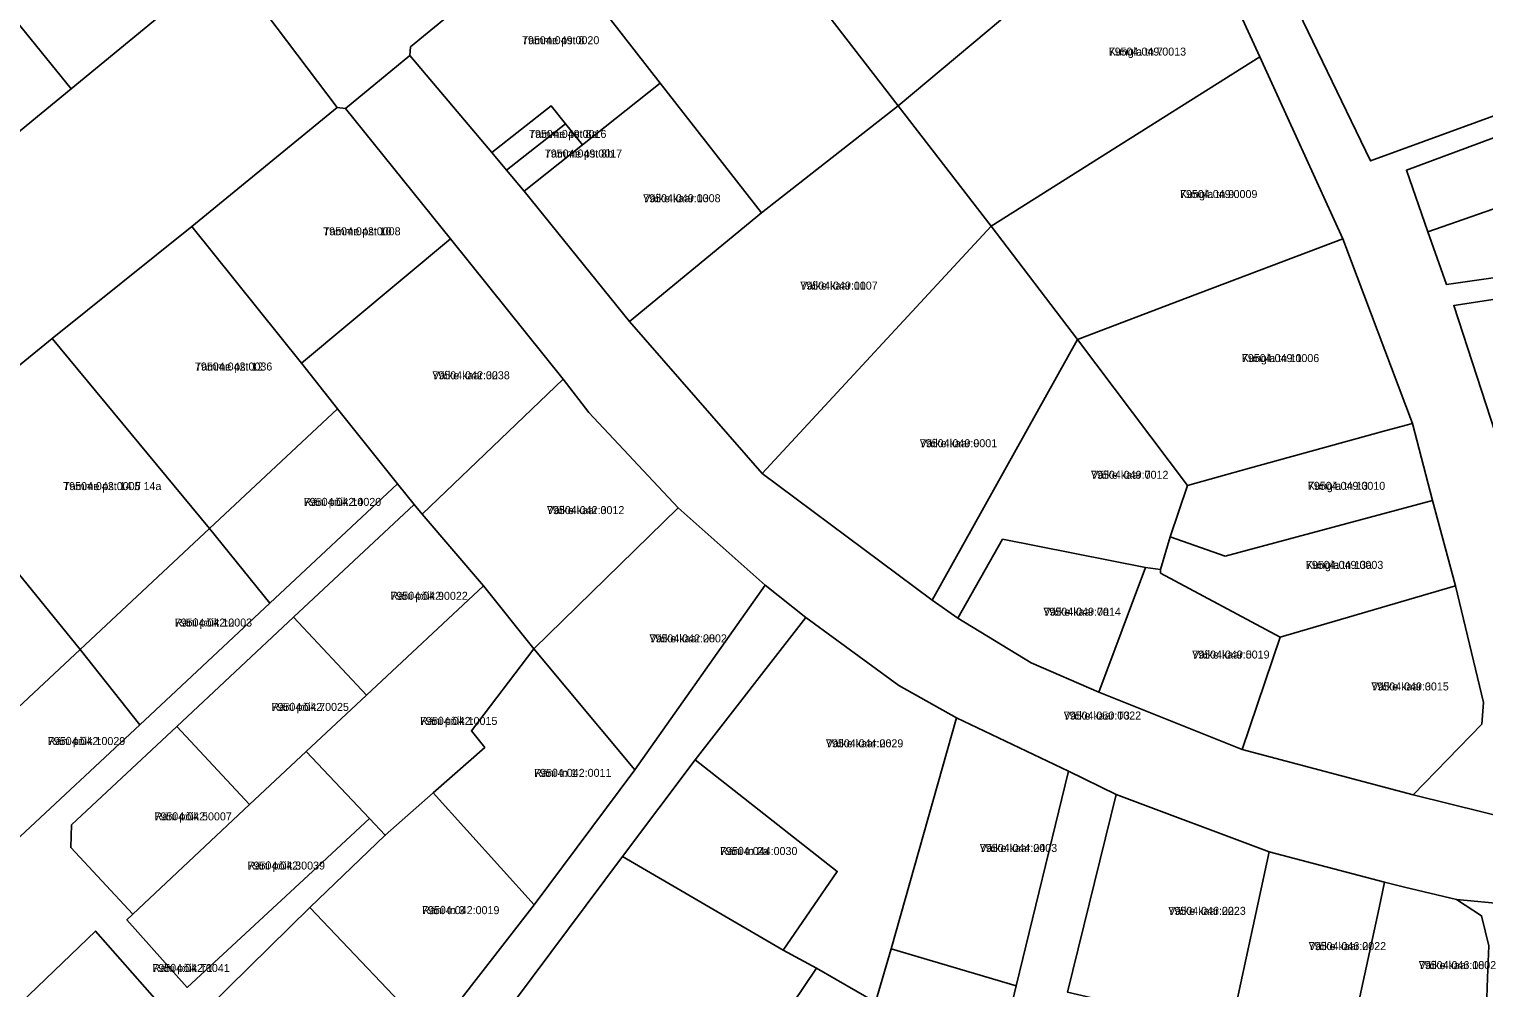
# Model space of a CAD drawing. Extents: x 643847 to 663718, y 6468443 to 6482775.
# Drawn here: x 658538 to 658810.6, y 6472429.5 to 6472609.2 of the extents above; entities that cross this region are included whole.
import ezdxf

# ---------------------------------------------------------------- set-up
doc = ezdxf.new("R2010")
doc.units = 0
for name, color, linetype in [('L_AADRESS', 7, 'Continuous'), ('PIIR', 7, 'Continuous'), ('TUNNUS', 7, 'Continuous')]:
    doc.layers.add(name, color=color, linetype=linetype)

msp = doc.modelspace()

# ---------------------------------------------------------------- linework, layer by layer
at = {"layer": 'PIIR'}
for points in [[(658772.27, 6472620.06), (658755.3, 6472648.11), (658745.1, 6472662.88), (658737.93, 6472672.19), (658724.79, 6472688.33), (658692.31, 6472729.24), (658604.24, 6472838.73), (658755.84, 6472964.06), (658773.4, 6472963.29), (658799.85, 6472926.02), (658816.91, 6472900.46), (658832.39, 6472875), (658856.2, 6472832.8), (658875.04, 6472794.43), (658903.22, 6472731.56), (658934.79, 6472638.51), (658936.46, 6472627.63), (658912.32, 6472622.52), (658875.54, 6472613.95), (658863.46, 6472610.64), (658844.95, 6472604.41), (658819.16, 6472595.4), (658789.38, 6472584.53)], [(658664.88, 6472694.99), (658690.31, 6472715.72), (658711.17, 6472689.65), (658686.36, 6472669.22), (658660.16, 6472647.63), (658634.79, 6472626.74), (658609.52, 6472605.92), (658609.35, 6472604.32), (658597.33, 6472594.39), (658595.74, 6472594.56), (658574.99, 6472622.05), (658588.09, 6472632.39), (658613.52, 6472653.29), (658638.86, 6472674.11)], [(658660.16, 6472647.63), (658686.36, 6472669.22), (658698.44, 6472653.06), (658725.82, 6472615.78), (658700.85, 6472594.87), (658687.88, 6472611.7)], [(658545.91, 6472598.05), (658521.25, 6472628.49), (658550.81, 6472652.12), (658574.99, 6472622.05)], [(658660.16, 6472647.63), (658687.88, 6472611.7), (658700.85, 6472594.87), (658675.23, 6472574.82), (658656.3, 6472599.13), (658634.79, 6472626.74)], [(658751.04, 6472636.25), (658761.74, 6472619.06), (658768.65, 6472604.06), (658742.65, 6472587.65), (658718.31, 6472572.3), (658700.85, 6472594.87), (658725.82, 6472615.78)], [(658545.91, 6472598.05), (658521.24, 6472577.81), (658494.24, 6472610.79), (658519.09, 6472631.13), (658521.25, 6472628.49)], [(658609.52, 6472605.92), (658634.79, 6472626.74), (658656.3, 6472599.13), (658641.69, 6472587.52), (658638.55, 6472591.47), (658635.82, 6472594.89), (658624.73, 6472586.08), (658609.35, 6472604.32)], [(658545.91, 6472598.05), (658574.99, 6472622.05), (658595.74, 6472594.56), (658568.5, 6472572.25), (658542.34, 6472551.27), (658516.97, 6472530.54), (658492.26, 6472510.34), (658467.24, 6472489.9), (658500.72, 6472449.11), (658497.58, 6472446.34), (658463.95, 6472487.22), (658456.24, 6472480.86), (658441.09, 6472468.41), (658456.62, 6472449.67), (658451.75, 6472445.76), (658436.48, 6472464.66), (658402.49, 6472436.71), (658382.4, 6472464.28), (658421.65, 6472496.43), (658443.3, 6472514.33), (658446.9, 6472516.98), (658471.09, 6472536.95), (658496.32, 6472557.43), (658521.24, 6472577.81)], [(658784.17, 6472569.95), (658755.16, 6472558.94), (658734.45, 6472551.07), (658718.31, 6472572.3), (658742.65, 6472587.65), (658768.65, 6472604.06)], [(658630.8, 6472578.87), (658656.3, 6472599.13), (658675.23, 6472574.82), (658650.52, 6472554.44)], [(658842.35, 6472599.98), (658847.97, 6472584.14), (658823.08, 6472578.54), (658817.69, 6472577.34), (658800.12, 6472571.23), (658796.11, 6472582.83)], [(658595.74, 6472594.56), (658597.33, 6472594.39), (658616.96, 6472569.92), (658589.06, 6472546.62), (658568.5, 6472572.25)], [(658624.73, 6472586.08), (658635.82, 6472594.89), (658638.55, 6472591.47), (658627.5, 6472582.78)], [(658650.52, 6472554.44), (658675.23, 6472574.82), (658700.85, 6472594.87), (658718.31, 6472572.3), (658675.38, 6472525.95)], [(658627.5, 6472582.78), (658638.55, 6472591.47), (658641.69, 6472587.52), (658630.8, 6472578.87)], [(658800.12, 6472571.23), (658817.69, 6472577.34), (658823.08, 6472578.54), (658825.41, 6472564.5), (658803.59, 6472561.34)], [(658568.5, 6472572.25), (658589.06, 6472546.62), (658595.84, 6472538.07), (658571.85, 6472515.64), (658542.34, 6472551.27)], [(658675.38, 6472525.95), (658718.31, 6472572.3), (658734.45, 6472551.07), (658707.22, 6472502.17)], [(658638.11, 6472543.6), (658611.68, 6472518.28), (658610.2, 6472520.13), (658607.08, 6472524.02), (658595.84, 6472538.07), (658589.06, 6472546.62), (658616.96, 6472569.92)], [(658792.28, 6472533.99), (658766.73, 6472526.92), (658755.06, 6472523.69), (658734.45, 6472551.07), (658755.16, 6472558.94), (658784.17, 6472569.95), (658797.25, 6472535.28)], [(658804.97, 6472557.4), (658854.99, 6472565.14), (658876.34, 6472568.45), (658878.6, 6472557.61), (658858.72, 6472554.5), (658860.33, 6472534.01), (658813.59, 6472530.95)], [(658542.34, 6472551.27), (658571.85, 6472515.64), (658547.6, 6472492.96), (658516.97, 6472530.54)], [(658734.45, 6472551.07), (658755.06, 6472523.69), (658751.85, 6472514.08), (658750.05, 6472507.91), (658747.19, 6472508.3), (658720.43, 6472513.62), (658712.08, 6472498.8), (658707.22, 6472502.17)], [(658642.88, 6472537.35), (658659.62, 6472519.52), (658632.61, 6472493.04), (658623.15, 6472504.86), (658611.68, 6472518.28), (658638.11, 6472543.6)], [(658571.85, 6472515.64), (658595.84, 6472538.07), (658607.08, 6472524.02), (658583.16, 6472501.65)], [(658801, 6472520.86), (658762.12, 6472510.45), (658751.85, 6472514.08), (658755.06, 6472523.69), (658766.73, 6472526.92), (658792.28, 6472533.99), (658797.25, 6472535.28)], [(658516.97, 6472530.54), (658547.6, 6472492.96), (658524.3, 6472471.18), (658492.26, 6472510.34)], [(658611.68, 6472518.28), (658623.15, 6472504.86), (658601.24, 6472484.37), (658587.58, 6472498.97), (658610.2, 6472520.13)], [(658805.3, 6472504.85), (658772.43, 6472495.25), (658750.03, 6472507.27), (658750.05, 6472507.91), (658751.85, 6472514.08), (658762.12, 6472510.45), (658801, 6472520.86)], [(658675.94, 6472505), (658651.54, 6472470.39), (658632.61, 6472493.04), (658659.62, 6472519.52)], [(658558.76, 6472478.84), (658547.6, 6472492.96), (658571.85, 6472515.64), (658583.16, 6472501.65)], [(658725.77, 6472490.45), (658712.08, 6472498.8), (658720.43, 6472513.62), (658747.19, 6472508.3), (658738.5, 6472484.92)], [(658772.43, 6472495.25), (658765.31, 6472474.18), (658738.5, 6472484.92), (658747.19, 6472508.3), (658750.05, 6472507.91), (658750.03, 6472507.27)], [(658601.8, 6472461.23), (658589.92, 6472473.79), (658601.24, 6472484.37), (658623.15, 6472504.86), (658632.61, 6472493.04), (658620.92, 6472477.71), (658623.39, 6472474.58), (658613.75, 6472466.04), (658604.75, 6472458.12)], [(658797.4, 6472465.67), (658765.31, 6472474.18), (658772.43, 6472495.25), (658805.3, 6472504.85), (658810.56, 6472483.03), (658810.23, 6472478.93)], [(658601.24, 6472484.37), (658589.92, 6472473.79), (658579.33, 6472463.88), (658565.68, 6472478.49), (658587.58, 6472498.97)], [(658683.56, 6472498.95), (658700.99, 6472486.21), (658711.83, 6472480.12), (658699.53, 6472436.84), (658696.61, 6472426.81), (658685.57, 6472433.21), (658679.29, 6472436.56), (658689.45, 6472451.33), (658662.83, 6472472.25)], [(658524.3, 6472471.18), (658547.6, 6472492.96), (658558.76, 6472478.84), (658535.48, 6472457.07)], [(658613.75, 6472466.04), (658623.39, 6472474.58), (658620.92, 6472477.71), (658632.61, 6472493.04), (658651.54, 6472470.39), (658632.69, 6472445.07)], [(658732.79, 6472470.1), (658722.96, 6472429.9), (658699.53, 6472436.84), (658711.83, 6472480.12)], [(658565.68, 6472478.49), (658579.33, 6472463.88), (658557.49, 6472443.32), (658545.82, 6472455.8), (658545.94, 6472460.05)], [(658556.35, 6472442.25), (658557.49, 6472443.32), (658579.33, 6472463.88), (658589.92, 6472473.79), (658601.8, 6472461.23), (658591.19, 6472451.35), (658567.62, 6472429.58)], [(658649.21, 6472454.1), (658662.83, 6472472.25), (658689.45, 6472451.33), (658679.29, 6472436.56)], [(658613.57, 6472420.43), (658590.62, 6472444.56), (658604.75, 6472458.12), (658613.75, 6472466.04), (658632.69, 6472445.07)], [(658770.38, 6472454.99), (658763.59, 6472423.51), (658763.18, 6472421.55), (658732.62, 6472428.68), (658741.74, 6472465.78)], [(658792, 6472449.32), (658790.99, 6472444.5), (658785.31, 6472418.32), (658763.59, 6472423.51), (658770.38, 6472454.99)], [(658649.21, 6472454.1), (658679.29, 6472436.56), (658685.57, 6472433.21), (658672.18, 6472413.3), (658663.79, 6472401.54), (658659.08, 6472405.4), (658628.98, 6472426.98)], [(658795.77, 6472448.4), (658805.49, 6472446.06), (658810.18, 6472443.01), (658811.53, 6472437.37), (658811.33, 6472431.37), (658810.87, 6472418.24), (658785.31, 6472418.32), (658790.99, 6472444.5), (658792, 6472449.32)], [(658595.52, 6472397.92), (658571.61, 6472425.87), (658590.62, 6472444.56), (658613.57, 6472420.43)], [(658550.48, 6472440.15), (658566.66, 6472421.74), (658544.3, 6472401.26), (658532.35, 6472414.77), (658528.58, 6472419.18)], [(658718.2, 6472409.58), (658693.2, 6472415.36), (658696.61, 6472426.81), (658699.53, 6472436.84), (658722.96, 6472429.9)], [(658672.49, 6472395.79), (658663.79, 6472401.54), (658672.18, 6472413.3), (658685.57, 6472433.21), (658696.61, 6472426.81), (658693.2, 6472415.36), (658681.24, 6472394.43), (658679.22, 6472390.99)]]:
    msp.add_lwpolyline(points, close=True, dxfattribs=at)
for points in [[(658823.86, 6472459.15), (658797.4, 6472465.67), (658810.23, 6472478.93), (658810.56, 6472483.03), (658805.3, 6472504.85), (658801, 6472520.86), (658797.25, 6472535.28), (658784.17, 6472569.95), (658768.65, 6472604.06), (658761.74, 6472619.06)], [(658772.27, 6472620.06), (658789.38, 6472584.53), (658819.16, 6472595.4)], [(658842.71, 6472442.54), (658805.49, 6472446.06), (658795.77, 6472448.4), (658792, 6472449.32), (658770.38, 6472454.99), (658741.74, 6472465.78), (658732.79, 6472470.1), (658711.83, 6472480.12), (658700.99, 6472486.21), (658683.56, 6472498.95), (658675.94, 6472505), (658659.62, 6472519.52), (658642.88, 6472537.35), (658638.11, 6472543.6), (658616.96, 6472569.92), (658597.33, 6472594.39), (658609.35, 6472604.32), (658624.73, 6472586.08), (658627.5, 6472582.78), (658630.8, 6472578.87), (658650.52, 6472554.44), (658675.38, 6472525.95), (658707.22, 6472502.17), (658712.08, 6472498.8), (658725.77, 6472490.45), (658738.5, 6472484.92), (658765.31, 6472474.18), (658797.4, 6472465.67), (658823.86, 6472459.15)], [(658842.35, 6472599.98), (658796.11, 6472582.83), (658800.12, 6472571.23), (658803.59, 6472561.34), (658825.41, 6472564.5)], [(658854.99, 6472565.14), (658804.97, 6472557.4), (658813.59, 6472530.95)], [(658535.48, 6472457.07), (658558.76, 6472478.84), (658583.16, 6472501.65), (658607.08, 6472524.02), (658610.2, 6472520.13), (658587.58, 6472498.97), (658565.68, 6472478.49), (658545.94, 6472460.05), (658545.82, 6472455.8), (658557.49, 6472443.32), (658556.35, 6472442.25), (658567.62, 6472429.58), (658591.19, 6472451.35), (658601.8, 6472461.23), (658604.75, 6472458.12), (658590.62, 6472444.56), (658571.61, 6472425.87), (658595.52, 6472397.92), (658591.44, 6472393.27), (658566.66, 6472421.74), (658550.48, 6472440.15), (658528.58, 6472419.18)], [(658518.27, 6472377.49), (658549.04, 6472345.11), (658571.16, 6472369.23), (658591.44, 6472393.27), (658595.52, 6472397.92), (658613.57, 6472420.43), (658632.69, 6472445.07), (658651.54, 6472470.39), (658675.94, 6472505), (658683.56, 6472498.95), (658662.83, 6472472.25), (658649.21, 6472454.1), (658628.98, 6472426.98), (658612.56, 6472406.46), (658608.83, 6472401.76), (658599.47, 6472390.45), (658588.28, 6472377.09), (658567.38, 6472353.17), (658545.01, 6472328.73), (658510.27, 6472292.72)], [(658718.2, 6472409.58), (658722.96, 6472429.9), (658732.79, 6472470.1), (658741.74, 6472465.78), (658732.62, 6472428.68)], [(658811.53, 6472437.37), (658810.18, 6472443.01), (658805.49, 6472446.06), (658842.71, 6472442.54)]]:
    msp.add_lwpolyline(points, dxfattribs=at)

# ---------------------------------------------------------------- texts
at = {"layer": 'L_AADRESS'}
for s, p in [('Tamme pst 8', (658630.37, 6472606.41)), ('Kungla tn 7', (658740.32, 6472604.28)), ('Tamme pst 8a', (658631.7, 6472588.84)), ('Tamme pst 8b', (658634.64, 6472585.17)), ('Väike kaar 13', (658653.09, 6472576.79)), ('Kungla tn 9', (658753.68, 6472577.57)), ('Tamme pst 10', (658593.13, 6472570.59)), ('Väike kaar 11', (658682.53, 6472560.41)), ('Kungla tn 11', (658765.27, 6472546.82)), ('Tamme pst 12', (658569.09, 6472545.24)), ('Väike kaar 32', (658613.59, 6472543.6)), ('Väike kaar 9', (658704.92, 6472530.86)), ('Väike kaar 7', (658737.01, 6472524.94)), ('Tamme pst 14 // 14a', (658544.41, 6472522.82)), ('Kungla tn 13', (658777.63, 6472522.87)), ('Räni põik 14', (658589.5, 6472519.86)), ('Väike kaar 30', (658635.06, 6472518.32)), ('Kungla tn 13a', (658777.27, 6472508.05)), ('Räni põik 9', (658605.72, 6472502.25)), ('Räni põik 12', (658565.31, 6472497.24)), ('Väike kaar 7a', (658728.09, 6472499.27)), ('Väike kaar 28', (658654.27, 6472494.27)), ('Väike kaar 5', (658755.96, 6472491.24)), ('Väike kaar 3', (658789.54, 6472485.26)), ('Räni põik 7', (658583.45, 6472481.42)), ('Räni põik 1', (658611.27, 6472478.8)), ('Väike kaar T3', (658731.89, 6472479.8)), ('Räni põik 10', (658541.54, 6472475.02)), ('Väike kaar 26', (658687.33, 6472474.6)), ('Räni tn 1', (658632.64, 6472469.06)), ('Räni põik 5', (658561.51, 6472460.9)), ('Räni tn 2a', (658667.49, 6472454.4)), ('Väike kaar 24', (658716.16, 6472454.98)), ('Räni põik 3', (658578.96, 6472451.68)), ('Räni tn 3', (658611.65, 6472443.32)), ('Väike kaar 22', (658751.5, 6472443.19)), ('Väike kaar 20', (658777.8, 6472436.58)), ('Räni põik T1', (658561.12, 6472432.47)), ('Väike kaar 18', (658798.42, 6472433.02))]:
    msp.add_text(s, height=1.5, dxfattribs=at).set_placement(p)
at = {"layer": 'TUNNUS'}
for s, p in [('79504:049:0020', (658630.37, 6472606.41)), ('79504:049:0013', (658740.32, 6472604.28)), ('79504:049:0016', (658631.7, 6472588.84)), ('79504:049:0017', (658634.64, 6472585.17)), ('79504:049:0008', (658653.09, 6472576.79)), ('79504:049:0009', (658753.68, 6472577.57)), ('79504:042:0008', (658593.13, 6472570.59)), ('79504:049:0007', (658682.53, 6472560.41)), ('79504:049:0006', (658765.27, 6472546.82)), ('79504:042:0036', (658569.09, 6472545.24)), ('79504:042:0038', (658613.59, 6472543.6)), ('79504:049:0001', (658704.92, 6472530.86)), ('79504:049:0012', (658737.01, 6472524.94)), ('79504:042:0005', (658544.41, 6472522.82)), ('79504:049:0010', (658777.63, 6472522.87)), ('79504:042:0020', (658589.5, 6472519.86)), ('79504:042:0012', (658635.06, 6472518.32)), ('79504:049:0003', (658777.27, 6472508.05)), ('79504:042:0022', (658605.72, 6472502.25)), ('79504:042:0003', (658565.31, 6472497.24)), ('79504:049:0014', (658728.09, 6472499.27)), ('79504:042:0002', (658654.27, 6472494.27)), ('79504:049:0019', (658755.96, 6472491.24)), ('79504:049:0015', (658789.54, 6472485.26)), ('79504:042:0025', (658583.45, 6472481.42)), ('79504:042:0015', (658611.27, 6472478.8)), ('79504:050:0022', (658731.89, 6472479.8)), ('79504:042:0029', (658541.54, 6472475.02)), ('79504:044:0029', (658687.33, 6472474.6)), ('79504:042:0011', (658632.64, 6472469.06)), ('79504:042:0007', (658561.51, 6472460.9)), ('79504:044:0030', (658667.49, 6472454.4)), ('79504:044:0003', (658716.16, 6472454.98)), ('79504:042:0039', (658578.96, 6472451.68)), ('79504:042:0019', (658611.65, 6472443.32)), ('79504:046:0023', (658751.5, 6472443.19)), ('79504:046:0022', (658777.8, 6472436.58)), ('79504:042:0041', (658561.12, 6472432.47)), ('79504:046:0002', (658798.42, 6472433.02))]:
    msp.add_text(s, height=1.5, dxfattribs=at).set_placement(p)

doc.saveas('drawing.dxf')
